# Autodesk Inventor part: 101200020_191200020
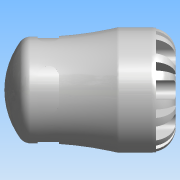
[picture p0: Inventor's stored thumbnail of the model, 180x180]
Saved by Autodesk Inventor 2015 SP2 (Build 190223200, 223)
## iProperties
Created: 2016-12
Part Number: 101200020_191200020
Material: PVC-Piping
Description: PLASSON END PLUG 20 SERIES 1
Document SubType Name: Modeling
Designer: KIM
Mass: 57.8335 g
Surface Area: 121.129 cm^2
Volume: 41.3096 cm^3
Density: 1.4 g/cm^3
Appearance: Smooth - White
Author: KIM
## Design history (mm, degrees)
derived "1012.ipt"
feature "Solid1::1012.ipt"
tag "TaggingFeature1"
body "Solid1"
other parameters: "d0" = 56, "d1" = 18.9, "d3" = 25, "d4" = 41, "d6" = 45, "d7" = 49.5, "d8" = 34.85, "d13" = 6.4, "d14" = 6.4, "d15" = 0, "d17" = 360 deg, "d19" = 8 deg, "d20" = 0.4, "d21" = 0.4, "d22" = 8 deg, "d24" = 0, "d26" = 360 deg, "d32" = 4.1, "d33" = 4.1, "d34" = 4.4, "d35" = 7, "d36" = 12.544, "d37" = 0, "d42" = 360 deg, "d45" = 5.95, "d46" = 0.4, "d48" = 0, "d49" = 0.41, "E_" = 41, "H_" = 56, "l_" = 45, "d9" = 8, "d11" = 41, "d12" = 25
